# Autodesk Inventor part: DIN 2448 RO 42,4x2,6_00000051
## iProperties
Created: 2006-03
Part Number: DIN 2448 RO 42,4x2,6_00000051
Material: Default
Document SubType Name: Modeling
Designer: Carlo
Stock Number: DIN 2448 RO 42,4x2,6
Mass: 507.137 g
Surface Area: 3914.3 cm^2
Volume: 507.137 cm^3
Density: 1 g/cm^3
G_L: 1590.000 mm
G_W: 42.400 mm
G_H: 42.400 mm
AFG_Item: 42.4 x 2.6
CSToolsMass: 1.0
CSToolsVolume: 507137.0
CSToolsArea: 3914.0
Author: Carlo
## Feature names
1. AFG_Detailed_DIN 2448 RO 42,4x2,6_00000051 [Extrusion]
2. AFG_Simplified_DIN 2448 RO 42,4x2,6_00000051 [Extrusion]
3. AFG_StartExtrusion_1 [Extrusion]
4. AFG_StartExtrusion_2 [Extrusion]
5. AFG_EndExtrusion_1 [Extrusion]
6. AFG_EndExtrusion_2 [Extrusion]
